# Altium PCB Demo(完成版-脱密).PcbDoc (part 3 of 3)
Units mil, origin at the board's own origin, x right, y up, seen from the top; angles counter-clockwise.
Board outline 2165.35 x 1574.8 mil, 6 copper layers (TOP, GND02, ART03, ART04, PWR05, BOTTOM); 172 components, 0 nets, 834 pads, 541 vias.
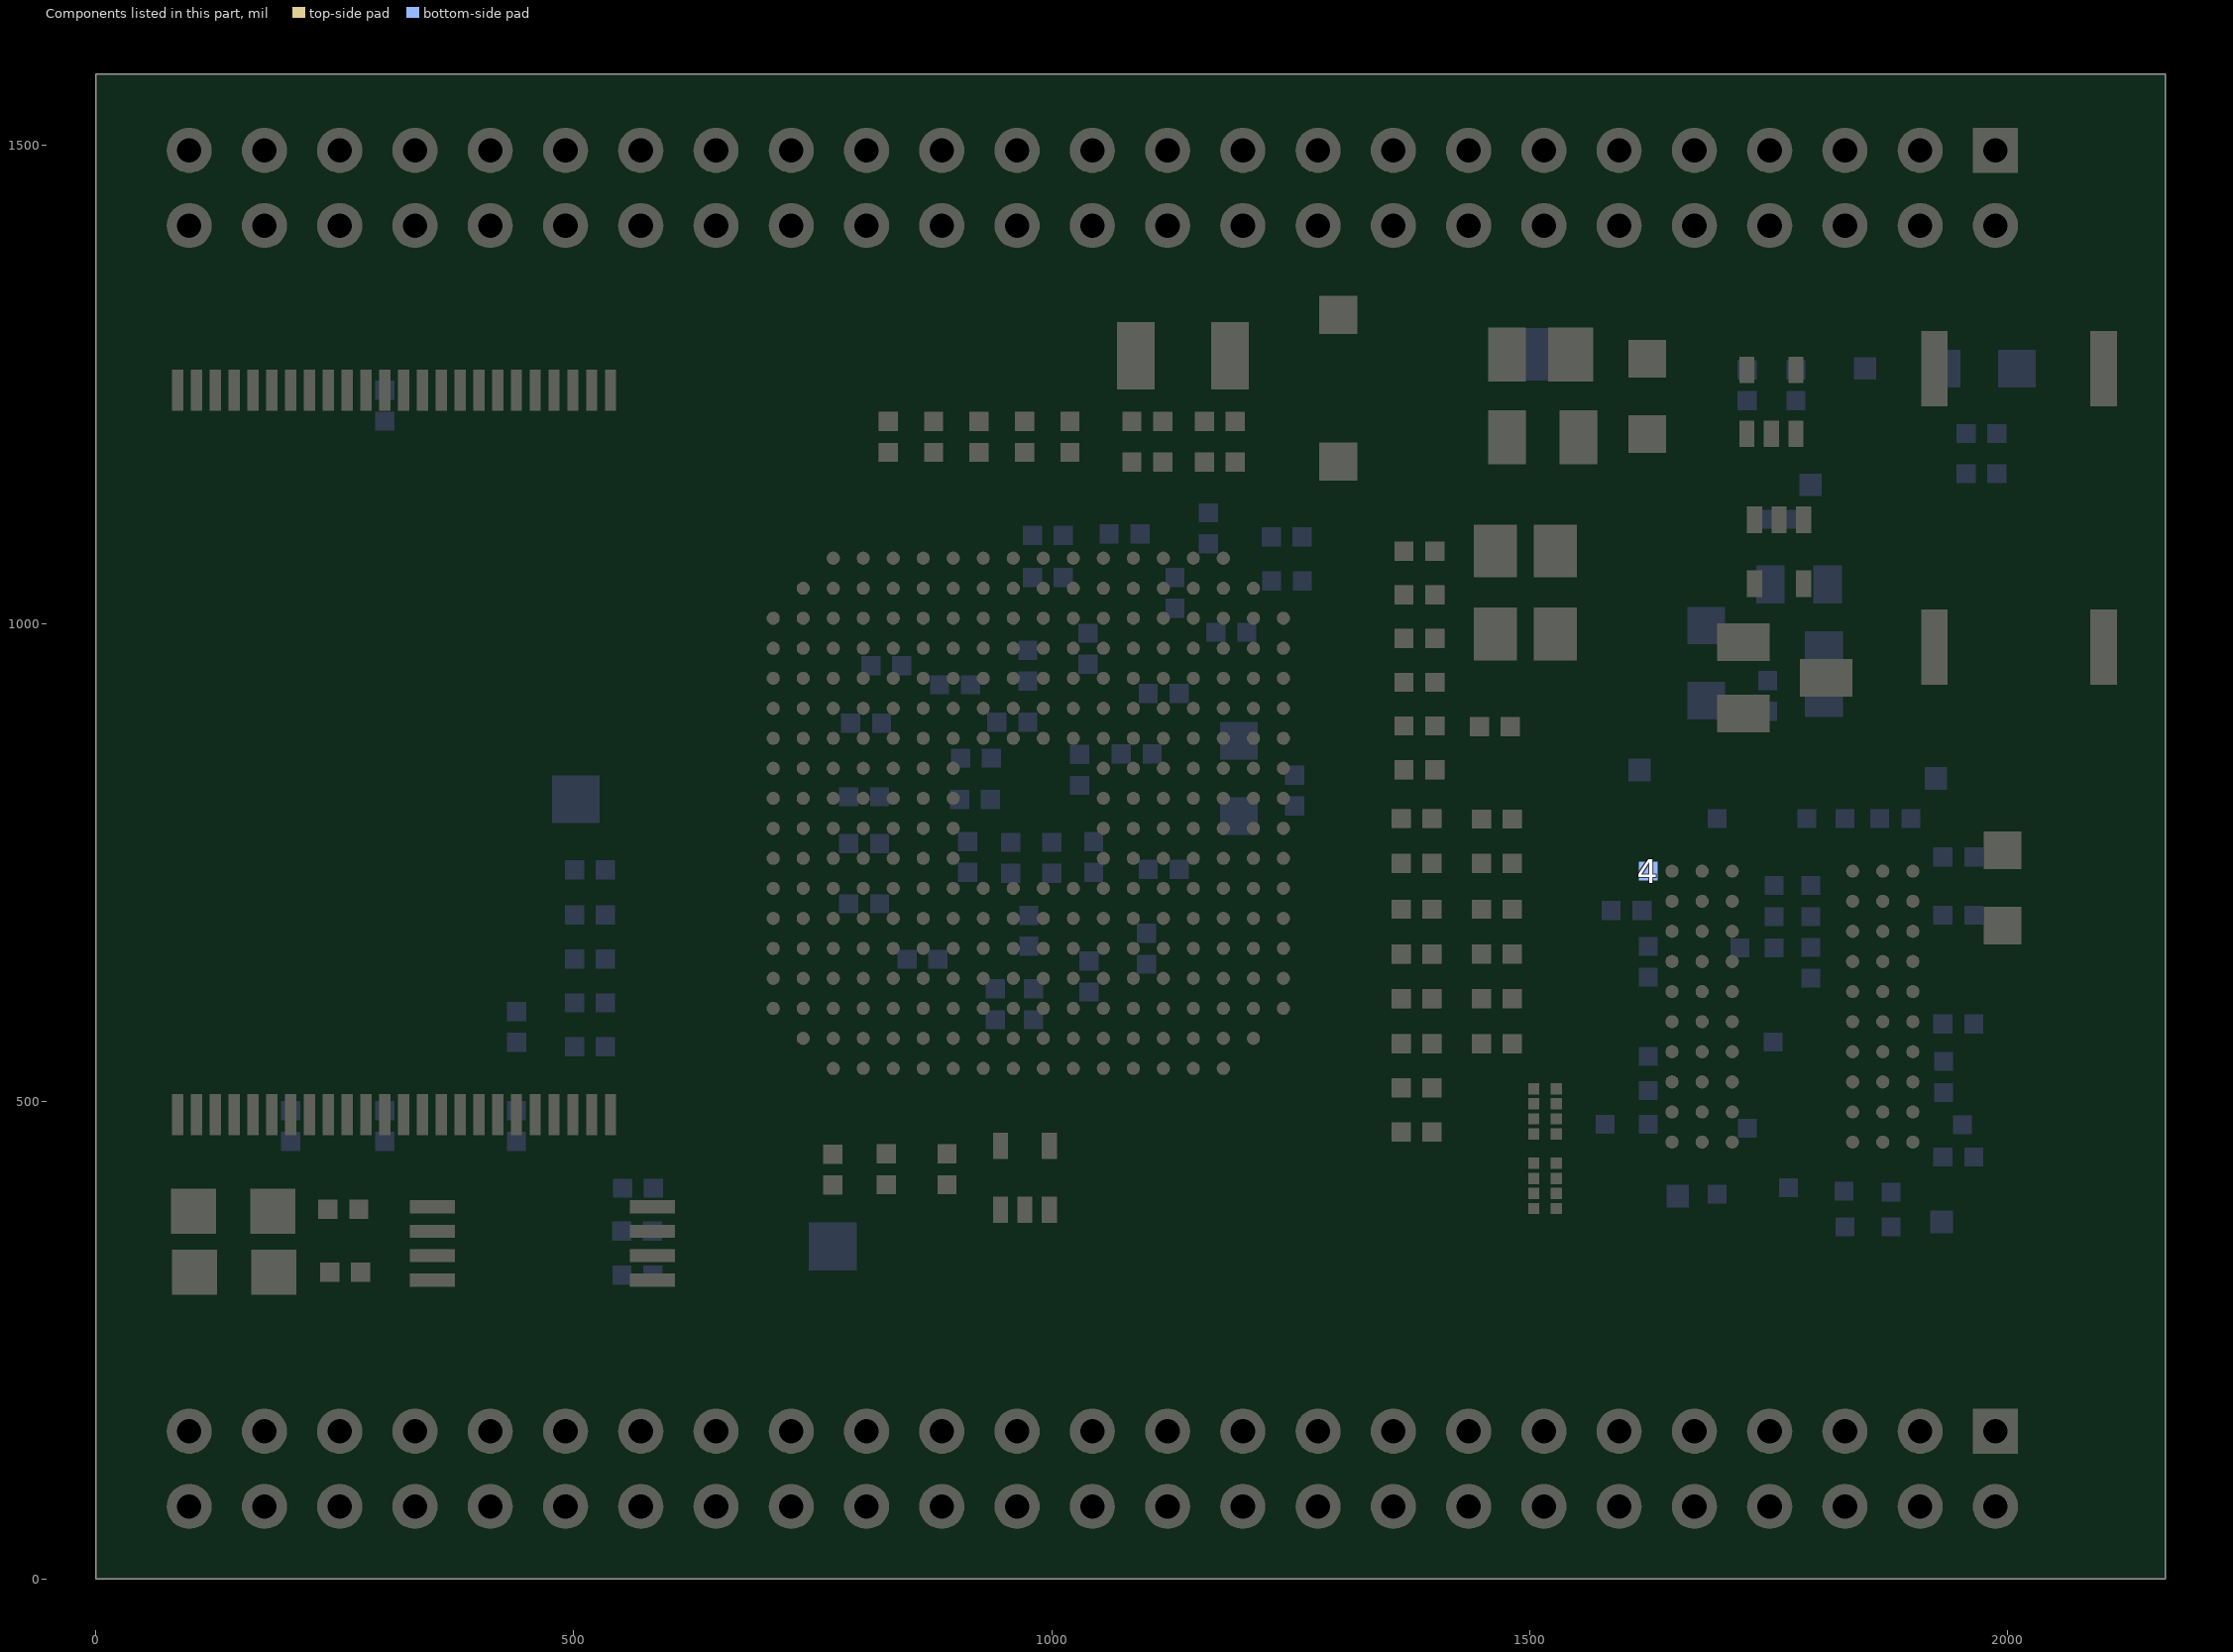
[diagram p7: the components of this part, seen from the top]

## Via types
v1: diameter 16, hole 8, TOP to BOTTOM, tented both sides, 541 vias

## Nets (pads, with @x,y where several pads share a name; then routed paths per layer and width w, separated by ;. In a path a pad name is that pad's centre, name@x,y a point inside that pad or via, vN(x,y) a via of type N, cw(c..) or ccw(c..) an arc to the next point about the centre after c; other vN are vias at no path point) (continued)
copper on no net: (continued)
  ART04 w6.2: 97.6,1416.26 97.01,1415.67 97.01,1367.73 111.01,1353.73 111.01,1164.73 165.01,1110.73 165.01,897.73 206.01,856.73 206.01,633.73 274.01,565.73 v1(385.01,565.73) 450.01,565.73 498.01,517.73 723.33,517.73 v1(724.3,518.7) ; 97.6,1495 141.01,1451.59 141.01,1356.73 ; v1(125.01,1073.73) 125.01,879.73 168.01,836.73 168.01,527.73 223.01,472.73 308.01,472.73 374.01,406.73 400.01,406.73 423.01,383.73 643.01,383.73 655.01,395.73 738.01,395.73 756.01,413.73 834.01,413.73 897,476.72 v1(897,503) ; v1(126.01,1120.73) 146.01,1100.73 146.01,888.73 187.01,847.73 187.01,630.73 270.01,547.73 444.01,547.73 492.01,499.73 739.01,499.73 775.01,535.73 804.13,535.73 v1(818.5,550.1) ; 141.01,1361.73 141.01,1356.73 ; 176.34,1416.26 178.01,1414.59 178.01,1338.73 142.01,1302.73 142.01,1173.73 201.01,1114.73 201.01,918.73 539.01,580.73 662.01,580.73 677.01,565.73 708.53,565.73 v1(724.3,581.5) ; 176.34,1495 215.01,1456.33 215.01,1346.73 162.01,1293.73 162.01,1178.73 177.01,1163.73 220.01,1163.73 241.01,1142.73 241.01,936.73 565.01,612.73 653.01,612.73 673.01,632.73 705.01,632.73 724.84,612.9 v1(787.1,612.9) ; v1(184.1,1204.87) 204.24,1184.73 244.01,1184.73 255.01,1173.73 255.01,1075.73 ; v1(203.69,555.14) 255.1,503.73 364.01,503.73 393.01,474.73 439.01,474.73 457.84,455.9 v1(691.9,455.9) v1@692.9,455.9 ; v1(203.78,525.14) 240.19,488.73 355.01,488.73 385.01,458.73 430.01,458.73 470.01,418.73 565.01,418.73 585.01,438.73 648.01,438.73 657.01,429.73 700.01,429.73 724.3,454.02 v1(724.3,455.9) ; v1@223.01,1118.73 223.01,928.73 554.54,597.2 859.54,597.2 865.6,591.14 865.6,565.8 v1(881.3,550.1) ; v1(223.47,1204.87) 249.87,1204.87 273.01,1181.73 273.01,963.73 560.01,676.73 654.01,676.73 670.74,660 890.74,660 900.01,650.73 908.01,650.73 912.7,646.04 v1(912.7,612.9) ; 255.01,1090.73 255.01,1075.73 ; 255.08,1416.26 257.01,1414.33 257.01,1366.73 ; 255.08,1495 292.01,1458.07 292.01,1387.73 274.01,1369.73 274.01,1261.73 386.86,1148.88 386.86,983.88 573.01,797.73 787.01,797.73 818.5,829.22 v1(818.5,864.1) ; 257.01,1373.73 257.01,1366.73 ; v1(285.01,589.73) 462.01,589.73 513.01,538.73 747.01,538.73 757.01,548.73 785.73,548.73 v1(818.5,581.5) ; v1(315.01,1084.87) 295.01,1064.87 295.01,972.73 576.34,691.4 922.34,691.4 928.4,685.34 928.4,597.2 v1(912.7,581.5) ; v1(316.01,1048.73) 316.01,976.73 569.94,722.8 683.94,722.8 703.01,703.73 802.01,703.73 821.08,722.8 950.94,722.8 959.8,713.94 959.8,597.2 v1(912.7,550.1) ; 333.82,1416.26 333.82,1375.92 357.01,1352.73 357.01,1210.73 404.71,1163.03 404.71,991.03 579.01,816.73 776.01,816.73 787.1,827.82 v1(787.1,864.1) ; 333.82,1495 374.01,1454.81 374.01,1217.73 422.56,1169.18 422.56,1000.18 577.01,845.73 705.93,845.73 v1(724.3,864.1) ; v1(350.32,1124.87) 350.32,988.42 584.54,754.2 935.54,754.2 972.01,717.73 972.01,583.73 928.4,540.12 v1(928.4,503) ; v1(365.01,525.73) 398.01,492.73 451.01,492.73 470.01,473.73 661.01,473.73 788.01,473.73 834.2,519.92 834.2,565.8 v1(849.9,581.5) ; v1(400.63,525.14) 419.04,506.73 461.01,506.73 481.01,486.73 689.01,486.73 755.13,486.73 v1(787.1,518.7) ; v1(411.01,426.73) 439.01,398.73 571.01,398.73 595.01,422.73 641.01,422.73 647.01,416.73 731.01,416.73 742.51,428.23 818.51,428.23 849.9,459.62 v1(849.9,550.1) ; 412.56,1495 458.26,1449.3 458.26,1160.73 ; 414.01,1421.73 414.01,1223.73 440.41,1197.33 440.41,1010.33 586.64,864.1 v1(661.5,864.1) ; 458.26,1288.73 458.26,1160.73 ; 491.3,1416.26 495.01,1412.55 495.01,1004.73 596.01,903.73 747.47,903.73 v1(755.7,895.5) ; 491.3,1495 531.01,1455.29 531.01,1025.99 v1(630.1,926.9) ; 570.04,1416.26 569.01,1415.23 569.01,1014.73 661.51,922.23 767.98,922.23 779.01,911.2 802.8,911.2 v1(818.5,926.9) ; 570.04,1495 609.01,1456.03 609.01,1388.73 592.01,1371.73 592.01,1011.73 664.51,939.23 774.77,939.23 v1(787.1,926.9) ; 647.01,1414.49 648.78,1416.26 648.78,1389.5 612.01,1352.73 612.01,1012.73 666.44,958.3 v1(724.3,958.3) ; 648.78,1495 686.01,1457.77 686.01,1386.73 630.01,1330.73 630.01,1015.73 674.01,971.73 706.33,971.73 v1(724.3,989.7) ; v1(692.9,864.1) 673.27,883.73 591.01,883.73 458.26,1016.48 458.26,1160.73 ; v1(692.9,989.7) 678.04,989.7 648.01,1019.73 648.01,1302.73 728.01,1382.73 728.01,1415.77 727.52,1416.26 ; v1(692.9,1021.1) 692.9,1262.62 806.26,1375.98 806.26,1416.26 809.73,1419.73 810.01,1419.73 ; v1(724.3,1115.3) 724.3,1239.02 858.01,1372.73 920.21,1372.73 963.74,1416.26 ; 727.52,1495 764.01,1458.51 764.01,1376.73 669.01,1281.73 669.01,1019.73 683.34,1005.4 740,1005.4 v1(755.7,989.7) ; v1(755.7,864.1) 776.02,884.42 810.7,884.42 837.48,911.2 956.48,911.2 966.01,920.73 966.01,1042.73 1008.01,1084.73 1088.14,1084.73 1123.14,1119.73 1260.01,1119.73 1297.01,1156.73 1297.01,1247.73 1317.01,1267.73 1317.01,1303.73 ; v1(755.7,1021.1) 708.01,1068.79 708.01,1251.73 842.01,1385.73 842.01,1459.25 806.26,1495 ; v1(755.7,1115.3) 740.01,1130.99 740.01,1225.73 869.01,1354.73 956.01,1354.73 1000.01,1398.73 1000.01,1458.73 963.74,1495 ; v1@755.7,1146.7 v1(755.7,1151) 755.7,1219.42 874.35,1338.07 964.29,1338.07 984.48,1358.26 1042.48,1416.26 ; v1@784.95,1148.85 772.01,1161.79 772.01,1207.73 886.88,1322.6 980.88,1322.6 1038.01,1379.73 1063.01,1379.73 1083.01,1399.73 1083.01,1449.73 1046.01,1486.73 ; v1(787.1,581.5) 769.33,563.73 742.01,563.73 732.01,553.73 664.01,553.73 652.51,565.23 522.51,565.23 444.01,643.73 v1(227.01,643.73) 227.01,866.73 182.01,911.73 182.01,1116.76 127.01,1171.76 127.01,1259.73 127.01,1313.73 141.01,1327.73 141.01,1356.73 ; v1(787.1,738.5) 765.33,716.73 708.01,716.73 686.24,738.5 575.24,738.5 336.01,977.73 336.01,1096.73 327.01,1105.73 307.01,1105.73 290.01,1122.73 290.01,1196.73 257.01,1229.73 257.01,1366.73 ; v1(787.1,1021.1) 787.1,1080.82 845.01,1138.73 845.01,1180.73 897.01,1232.73 897.01,1253.73 930.01,1286.73 986.01,1286.73 1045.01,1345.73 1076.01,1345.73 1108.89,1378.61 1145.89,1378.61 1159.01,1391.73 1159.01,1457.21 1121.22,1495 ; v1(787.1,1115.3) 809.01,1137.21 809.01,1189.73 852.01,1232.73 852.01,1248.73 872.52,1269.24 888.52,1269.24 922.09,1302.81 980.09,1302.81 1039.01,1361.73 1066.69,1361.73 1121.22,1416.26 ; v1(818.5,1021.1) 834.2,1036.8 834.2,1105.33 860.01,1131.14 860.01,1165.73 907.01,1212.73 939.01,1212.73 948.01,1221.73 948.01,1248.73 968.01,1268.73 990.01,1268.73 1051.01,1329.73 1089.01,1329.73 1125.01,1365.73 1185.01,1365.73 1199.96,1380.68 1199.96,1416.26 ; v1(849.9,801.3) 891.01,801.3 950.01,860.3 950.01,880.73 984.01,914.73 984.01,1039.73 1012.48,1068.2 1123.01,1068.2 1156.54,1101.73 1267.01,1101.73 1310.01,1144.73 1310.01,1238.73 1333.01,1261.73 1333.01,1310.73 ; v1(849.9,1021.1) 869.01,1040.21 869.01,1076.73 891.88,1099.6 961.88,1099.6 982.01,1119.73 1048.01,1119.73 1102.01,1173.73 1137.01,1173.73 1239.01,1173.73 1258.01,1192.73 1258.01,1262.73 1249.01,1271.73 1249.01,1353.73 1237.01,1365.73 1237.01,1453.73 1202.01,1488.73 ; v1(881.3,581.5) 897,597.2 897,621.74 890.14,628.6 732.14,628.6 715.01,645.73 661.01,645.73 642.01,626.73 583.01,626.73 255.01,954.73 255.01,1075.73 ; v1(881.3,989.7) 928.4,1036.8 928.4,1062.12 934.48,1068.2 971.48,1068.2 1006.01,1102.73 1083.01,1102.73 1139.01,1158.73 1258.01,1158.73 1274.01,1174.73 1274.01,1411.57 1278.7,1416.26 ; v1(1006.9,612.9) 1006.9,576.62 995.01,564.73 995.01,441.73 1120.01,316.73 1812.01,316.73 1916.73,421.45 v1(1916.73,473.07) ; v1(1038.3,581.5) 1038.3,594.44 1033.01,599.73 1029.01,599.73 1022.27,592.99 1022.27,565.47 1010.01,553.21 1010.01,446.73 1126.01,330.73 1806.01,330.73 1903.01,427.73 1903.01,450.73 1897.01,456.73 1859.01,456.73 1853.74,462 v1(1853.74,473.07) ; v1(1069.7,518.7) 1069.7,455.04 1153.01,371.73 1170.01,371.73 1174.56,371.73 1179.11,376.28 1179.11,383.18 1183.66,387.73 1192.76,387.73 1197.31,383.18 1197.31,376.28 1201.86,371.73 1210.96,371.73 1215.51,376.28 1215.51,383.18 1220.06,387.73 1229.16,387.73 1233.71,383.18 1233.71,376.28 1238.26,371.73 1247.36,371.73 1251.91,376.28 1251.91,383.18 1256.46,387.73 1265.56,387.73 1270.11,383.18 1270.11,376.28 1274.66,371.73 1283.76,371.73 1288.31,376.28 1288.31,383.18 1292.86,387.73 1301.96,387.73 1306.51,383.18 1306.51,376.28 1311.06,371.73 1320.16,371.73 1324.71,376.28 1324.71,383.18 1329.26,387.73 1338.36,387.73 1342.91,383.18 1342.91,376.28 1347.46,371.73 1356.56,371.73 1361.11,376.28 1361.11,383.18 1365.66,387.73 1374.76,387.73 1379.31,383.18 1379.31,376.28 1383.86,371.73 1392.96,371.73 1397.51,376.28 1397.51,383.18 1402.06,387.73 1411.16,387.73 1415.71,383.18 1415.71,376.28 1420.26,371.73 1427.01,371.73 1706.01,371.73 1791.6,457.32 1832.42,457.32 1838.01,451.73 1838.01,444.73 1834.85,441.57 v1(1822.24,441.57) ; v1(1069.7,550.1) 1056.67,537.07 1056.35,537.07 1042.01,522.73 1042.01,515.73 1053.01,504.73 1053.01,490.73 1043.01,480.73 1043.01,465.73 1053.01,455.73 1053.01,445.73 1140.01,358.73 1743.01,358.73 1748.01,363.73 1748.01,389.73 1782.01,423.73 1789.01,423.73 1793.01,419.73 1793.01,367.73 1798.01,362.73 1815.01,362.73 1824.01,371.73 1824.01,389.73 1816.01,397.73 1816.01,406.73 1822.01,412.73 1838.01,412.73 1844.01,406.73 1859.01,406.73 1869.01,416.73 1869.01,426.3 v1(1853.74,441.57) v1@1851.85,441.57 ; v1(1069.7,612.9) 1069.7,614.04 1043.01,640.73 1031.01,640.73 1026.01,635.73 1026.01,618.73 1029.01,615.73 1043.01,615.73 1054.01,604.73 1054.01,568.73 1026.01,540.73 1026.01,451.73 1134.01,343.73 1759.01,343.73 1771.01,355.73 v1(1771.01,386.73) v1@1771.01,389.73 ; v1(1069.7,989.7) 1085.4,1005.4 1353.01,1005.4 1382.34,1034.73 1558.01,1034.73 1575.01,1051.73 1624.01,1051.73 1646.29,1074.01 v1(1735,1074.01) ; v1(1069.7,1021.1) 1085.4,1036.8 1234.08,1036.8 1348.55,1151.27 1348.55,1310.27 1394.01,1355.73 1394.01,1458.43 1357.44,1495 ; v1(1101.1,518.7) 1101.1,477.64 1159.81,418.93 1500.81,418.93 1507.01,412.73 1507.01,406.73 1513.01,400.73 1525.01,400.73 1532.01,407.73 1532.01,429.73 1527.01,434.73 1513.01,434.73 1505.01,442.73 1505.01,452.73 1509.6,457.32 1527.01,457.32 1531.56,457.32 1536.11,461.87 1536.11,472.29 1540.66,476.84 1549.76,476.84 1554.31,472.29 1554.31,461.87 1558.86,457.32 1567.96,457.32 1572.51,461.87 1572.51,472.29 1577.06,476.84 1586.16,476.84 1590.71,472.29 1590.71,461.87 1595.26,457.32 1604.36,457.32 1608.91,461.87 1608.91,472.29 1613.46,476.84 1622.56,476.84 1627.11,472.29 1627.11,461.87 1631.66,457.32 1660.01,457.32 1712.01,457.32 v1(1727.76,441.57) ; v1(1101.1,581.5) 1085.4,565.8 1085.4,465.34 1147.01,403.73 1424.01,403.73 1441.01,386.73 1593.56,386.73 1598.11,391.28 1598.11,424.18 1602.66,428.73 1611.76,428.73 1616.31,424.18 1616.31,391.28 1620.86,386.73 1629.96,386.73 1634.51,391.28 1634.51,424.18 1639.06,428.73 1648.16,428.73 1652.71,424.18 1652.71,391.28 1657.26,386.73 1667.71,386.73 1672.26,391.28 1672.26,424.18 1676.81,428.73 1685.91,428.73 1690.46,424.18 1690.46,391.28 ; v1(1132.5,518.7) 1132.5,490.24 1141.51,481.23 1160.51,481.23 1167.51,474.23 1167.51,455.23 1174.01,448.73 1186.56,448.73 1191.11,453.28 1191.11,482.18 1195.66,486.73 1204.76,486.73 1209.31,482.18 1209.31,453.28 1213.86,448.73 1222.96,448.73 1227.51,453.28 1227.51,482.18 1232.06,486.73 1241.16,486.73 1245.71,482.18 1245.71,453.28 1250.26,448.73 1259.36,448.73 1263.91,453.28 1263.91,482.18 1268.46,486.73 1277.56,486.73 1282.11,482.18 1282.11,453.28 1286.66,448.73 1295.76,448.73 1300.31,453.28 1300.31,482.18 1304.86,486.73 1313.96,486.73 1318.51,482.18 1318.51,453.28 1323.06,448.73 1332.16,448.73 1336.71,453.28 1336.71,482.18 1341.26,486.73 1350.36,486.73 1354.91,482.18 1354.91,453.28 1359.46,448.73 1368.71,448.73 1373.26,453.28 1373.26,482.18 1377.81,486.73 1386.91,486.73 1391.46,482.18 1391.46,453.28 1396.01,448.73 1406.01,448.73 1410.01,452.73 1410.01,486.73 1421.01,497.73 1496.01,497.73 1508.01,509.73 1541.01,509.73 1552.01,520.73 1564.01,520.73 1573.01,511.73 1590.01,511.73 1599.01,520.73 1616.01,520.73 1625.01,511.73 1641.01,511.73 1649.6,520.32 1673.42,520.32 1679.01,514.73 1679.01,506.73 1676.85,504.57 v1(1664.76,504.57) ; v1(1132.5,550.1) 1132.5,562.22 1136.01,565.73 1144.01,565.73 1148.2,561.54 1148.2,511.54 1157.01,502.73 1312.01,502.73 1344.01,534.73 1392.01,534.73 1409.01,551.73 1428.01,551.73 1441.01,564.73 1460.01,564.73 1473.01,551.73 1775.01,551.73 1786.01,540.73 1802.01,540.73 1813.01,551.73 1833.01,551.73 1838.01,546.73 1838.01,526.73 1831.6,520.32 1768.6,520.32 1764.01,515.73 1764.01,493.73 1768.92,488.82 1832.92,488.82 1837.99,483.75 1837.99,476.71 1834.35,473.07 v1(1822.24,473.07) ; v1(1132.5,612.9) 1116.8,597.2 1116.8,482.94 1165.01,434.73 1419.01,434.73 1437.01,452.73 1468.73,452.73 v1(1484.01,468.01) ; v1(1163.9,518.7) 1304.98,518.7 1336.01,549.73 1383.01,549.73 1398.7,565.42 1410.7,565.42 1424.01,578.73 1534.01,578.73 1547.01,591.73 1581.27,591.73 1591,582 1626.28,582 1641.01,596.73 1695.01,596.73 1725.01,566.73 1818.01,566.73 1841.01,589.73 1855.01,589.73 1863.01,581.73 1875.01,581.73 1883.01,589.73 1911.16,589.73 1915.71,585.18 1915.71,542.28 1920.26,537.73 1929.36,537.73 1933.91,542.28 1933.91,585.18 1938.46,589.73 1954.01,589.73 1960.01,583.73 1960.01,511.73 1954.01,505.73 1912.6,505.73 1898.01,520.32 1869.49,520.32 v1(1853.74,504.57) ; v1(1163.9,550.1) 1180.27,533.73 1295.01,533.73 1325.39,564.11 1368.39,564.11 1380.01,575.73 1380.01,591.73 1388.02,599.74 1499,599.74 1506.01,592.73 1524.73,592.73 1540.73,608.73 1585.27,608.73 1598,596 1617.28,596 1633.01,611.73 1706.27,611.73 1737.27,580.73 1812.01,580.73 1838.01,606.73 1966.01,606.73 1977.01,595.73 1977.01,556.18 1981.56,551.63 1992.46,551.63 1997.01,547.08 1997.01,537.98 1992.46,533.43 1981.56,533.43 1977.01,528.88 1977.01,503.73 ; v1(1195.3,707.1) 1179.6,691.4 1123.34,691.4 1116.8,697.94 1116.8,715.52 1124.08,722.8 1257.08,722.8 1275.01,740.73 1275.01,754.73 1287.01,766.73 1627.01,766.73 1653.01,740.73 1704.01,740.73 1712.01,732.73 1712.01,709.3 v1(1696.26,693.54) ; v1(1195.3,738.5) 1195.3,767.3 1229.73,801.73 1299.01,801.73 1317.01,819.73 1365.01,819.73 1383.01,801.73 1706.16,801.73 1710.71,797.18 1710.71,780.28 1715.26,775.73 1724.36,775.73 1728.91,780.28 1728.91,797.18 1733.46,801.73 1805.01,801.73 1815.01,791.73 1815.01,779.73 1810.01,774.73 1755.01,774.73 1747.01,766.73 1747.01,744.29 v1(1727.76,725.03) ; v1(1226.71,675.7) 1206.88,655.88 1193.56,655.88 1189.01,651.33 1189.01,642.23 1193.56,637.68 1206.46,637.68 1211.01,633.13 1211.01,597 1216.01,592 1230,592 1235,587 1235,581 1228,574 1216.01,574 1211.01,569 1211.01,561.99 1219,554 1259.83,554 1289.11,583.28 1289.11,622.18 1293.66,626.73 1302.76,626.73 1307.31,622.18 1307.31,583.28 1311.86,578.73 1320.96,578.73 1325.51,583.28 1325.51,622.18 1330.06,626.73 1339.16,626.73 1343.71,622.18 1343.71,583.28 1348.26,578.73 1358.01,578.73 1365.01,585.73 1365.01,602 1376.48,613.47 1449.92,613.47 1467,630.55 v1(1664.76,630.55) ; v1(1226.71,707.1) 1242.41,691.4 1271.4,691.4 1305,725 1350.74,725 1370.01,705.73 1385.01,705.73 1398.01,718.73 1436.01,718.73 1447.01,707.73 1465.01,707.73 1476.01,718.73 1527.01,718.73 1537.01,708.73 1537.01,685.73 1546.01,676.73 1798.01,676.73 1805.01,683.73 1805.01,689.73 1799.01,695.73 1782.01,695.73 1776.01,701.73 1776.01,709.73 1782.01,715.73 1800.01,715.73 1805.01,720.73 1805.01,729.73 1796.01,738.73 1768.01,738.73 1755.01,725.73 1755.01,700.73 1747.82,693.54 v1(1727.76,693.54) ; v1(1226.71,738.5) 1272.93,784.73 1668.06,784.73 v1(1696.26,756.53) ; v1(1258.1,675.7) 1283.7,675.7 1319,711 1342,711 1358.27,694.73 1383,694.73 1392.73,685 1442.74,685 1465.7,662.04 1474.56,662.04 1479.11,666.59 1479.11,695.49 1483.66,700.04 1492.76,700.04 1497.31,695.49 1497.31,666.59 1501.86,662.04 1791.96,662.04 1822,632 1822,613 1816.79,607.79 1807.21,607.79 1802,613 1802,621 1796,627 1787,627 1782,622 1782,605 1774.73,597.73 1767,597.73 1759.26,605.47 v1(1759.26,630.54) ; v1(1258.1,707.1) 1263.03,707.1 1306.66,750.73 1352.16,750.73 1356.71,746.18 1356.71,737.28 1361.26,732.73 1370.36,732.73 1374.91,737.28 1374.91,746.18 1379.46,750.73 1388.56,750.73 1393.11,746.18 1393.11,737.28 1397.66,732.73 1443.16,732.73 1447.71,737.28 1447.71,746.18 1452.26,750.73 1461.36,750.73 1465.91,746.18 1465.91,737.28 1470.46,732.73 1479.56,732.73 1484.11,737.28 1484.11,746.18 1488.66,750.73 1497.76,750.73 1502.31,746.18 1502.31,737.28 1506.86,732.73 1530.01,732.73 1535.01,737.73 1535.01,746.73 1539.01,750.73 1549.01,750.73 1552.01,747.73 1552.01,697.73 1558.01,691.73 1568.56,691.73 1573.11,696.28 1573.11,743.18 1577.66,747.73 1586.76,747.73 1591.31,743.18 1591.31,696.28 1595.86,691.73 1604.96,691.73 1609.51,696.28 1609.51,743.18 1614.06,747.73 1623.16,747.73 1627.71,743.18 1627.71,696.28 1632.26,691.73 1641.01,691.73 1645.01,695.73 1645.01,702.73 1651.57,709.29 1680.51,709.29 v1(1696.26,725.03) ; v1@1260.09,646.3 v1(1258.1,644.3) 1258.1,631.82 1255.01,628.73 1247.01,628.73 1243.01,632.73 1243.01,655.73 1247.01,659.73 1271.01,659.73 1289.01,641.73 1300.01,641.73 1309.01,650.73 1321.01,650.73 1330.01,641.73 1352.55,641.73 1357.1,646.28 1357.1,669.18 1361.65,673.73 1370.75,673.73 1375.3,669.18 1375.3,646.28 1379.85,641.73 1394.01,641.73 1398.58,646.3 1712.01,646.3 v1(1727.76,630.54) ; 1278.7,1495 1317.01,1456.69 1317.01,1303.73 ; 1317.01,1308.73 1317.01,1303.73 ; 1333.01,1315.73 1333.01,1310.73 ; 1357.44,1416.26 1357.44,1362.16 1333.01,1337.73 1333.01,1310.73 ; v1(1427.39,514.01) 1417.29,514.01 1405.01,501.73 1350.01,501.73 1346.01,505.73 1346.01,514.73 1352.01,520.73 1398.01,520.73 1413.34,536.06 1441.16,536.06 1445.71,531.51 1445.71,518.61 1450.26,514.06 1459.36,514.06 1463.91,518.61 1463.91,531.51 1468.46,536.06 1495.68,536.06 1506.01,525.73 1528.01,525.73 1538.34,536.06 v1(1664.76,536.06) ; 1436.18,1416.26 1477,1375.44 1477,1311.73 v1(1552,1236.73) ; v1(1449.01,822.73) v1(1566.01,822.73) ; v1(1576.29,567.56) 1638.01,567.56 1654.18,583.73 1680.09,583.73 v1(1696.26,567.56) v1@1696.26,571.48 ; 1692.06,389.68 1690.46,391.28 ; v1(1696.26,473.07) 1761.67,473.07 1769.01,465.73 1769.01,456.73 1736.37,424.09 1721.37,424.09 1711.01,413.73 1711.01,398.73 1700.01,387.73 1694.01,387.73 1690.46,391.28 ; v1(1885.23,504.57) 1897.07,492.73 1930.16,492.73 1934.71,488.18 1934.71,475.28 1939.26,470.73 1948.36,470.73 1952.91,475.28 1952.91,488.18 1957.46,492.73 1968.01,492.73 1977.01,501.73
  ART04 w10: 972,532.73 972,558.83 ; v1(1430,847) 1572.74,847 1582.01,837.73 v1@1790.01,837.73
  ART04 w15: v1(1101.1,895.5) 1101.1,878.64 1110.01,869.73 1582.01,869.73 1591.01,860.73 1677.74,860.73 1690.01,873 v1(1742.01,873) v1(1803.01,873) ; v1(1132.5,895.5) 1256.01,895.5 1277.24,916.73 1417.01,916.73 1428.01,905.73 1483,905.73 1496,918.73 1570.01,918.73 v1(1602.01,886.73) v1(1628.01,886.73) v1(1651.01,886.73)
  BOTTOM w5: 771.01,723.31 771.01,754.2 ; v1(1195.3,612.9) 1195.3,627.3 1200,632 1200,636 1196,640 1186,640 1183,643 1183,654 1189,660 1268,660 1280.5,672.5 1321.5,672.5 v1(1330,664) ; v1(1226.98,770.18) 1211.01,754.21 1211.01,698.39 1218,691.4 1268.6,691.4 1275.5,684.5 1321.5,684.5 v1(1330,693) ; v1(1423,669) 1432,678 1446.97,678 1459,690.03 1459,722.03 1461.97,725 1481.03,725 1490,716.03 1490,629.24 1486.26,625.5 1458.76,625.5 1448,614.74 1448,580.26 1458.76,569.5 1472.26,569.5 1476,565.76 1476,556.24 1472.26,552.5 1458.76,552.5 1448,541.74 1448,503.03 1467.03,484 1511.97,484 1528,500.03 1528,577.03 1537.97,587 1553.74,587 1564.5,597.76 1564.5,655.26 1568.24,659 1577.76,659 1581.5,655.26 1581.5,597.76 1592.26,587 1705,587 1715,577 1715,554.8 v1(1696.26,536.06) ; v1(1423,700.91) 1433.91,690 1442,690 1447,695 1447,727 1457,737 1486,737 1502,721 1502,624.26 1491.24,613.5 1463.74,613.5 1460,609.76 1460,585.24 1463.74,581.5 1477.24,581.5 1488,570.74 1488,551.26 1477.24,540.5 1463.74,540.5 1460,536.76 1460,508 1472,496 1507,496 1516,505 1516,582 1533,599 1548.76,599 1552.5,602.74 1552.5,660.24 1563.26,671 1582.74,671 1593.5,660.24 1593.5,602.74 1597.24,599 1709.97,599 1727.76,581.21 v1(1727.76,536.06)
  BOTTOM w5.7: 203.73,490.14 203.73,525.09 v1(203.78,525.14) ; v1(385.01,565.73) 413.15,593.87 440.01,593.87 ; 439.95,490.14 v1(440,525.14) v1(440,525.14) 440,561.58 ; 500.72,742 500.72,814.72 502,816 ; 533,557 557.5,581.5 v1(692.9,581.5) ; 533,603 538.8,597.2 802.8,597.2 v1(818.5,612.9) v1@818.5,615.11 ; 533,649 537.7,644.3 v1(630.1,644.3) ; 533,695 552.74,695 571.01,676.73 636.28,676.73 653.01,660 708.6,660 v1(724.3,675.7) ; 533,742 583.6,691.4 740,691.4 v1(755.7,675.7) ; 582.59,318 582.31,318.28 582.31,364 625.82,364 v1(626,364.18) ; v1(755.7,581.5) 803.12,534.08 v1(803.12,444.6) ; 771,348 v1(771,385.74) ; v1(827.01,476.73) 827.01,529.54 834.2,536.73 834.2,597.2 v1(849.9,612.9) ; 829,1179 v1(829,1151) 865.6,1114.4 865.6,1101.73 896.81,1070.52 896.81,973.81 v1(881.3,958.3) ; v1(876.5,1151) 888.3,1151 v1(924,1115.3) ; v1(924,1154) 941.01,1136.99 941.01,1104.73 928.4,1092.12 928.4,1005.4 v1(944.1,989.7) ; v1@971.5,1151 v1(971.5,1154) 971.5,1179 ; 975,1043.14 979.86,1048 ; v1@1019,1151 v1(1019,1154) 1019,1179 ; v1(1101.1,958.3) 1116.8,974 1116.8,1003.66 1129,1015.86 ; v1(1132.5,675.7) 1132.5,642.22 1116.8,626.52 1116.8,502 1130,488.8 1130,413 1167,376 1428.71,376 v1(1456.01,403.3) ; v1(1163.9,612.9) 1179.6,597.2 1187.8,597.2 1195,590 1195,579 1179.6,563.6 1179.6,462.4 1207.21,434.79 1220,434.79 1238.43,434.79 1242.85,430.36 1242.85,417.76 1247.28,413.34 1256.12,413.34 1260.55,417.76 1260.55,430.36 1264.97,434.79 1273.82,434.79 1278.25,430.36 1278.25,417.76 1282.68,413.34 1291.53,413.34 1295.95,417.76 1295.95,430.36 1300.38,434.79 1309.22,434.79 1313.65,430.36 1313.65,417.76 1318.07,413.34 1326.93,413.34 1331.35,417.76 1331.35,430.36 1335.78,434.79 1344.62,434.79 1349.05,430.36 1349.05,417.76 1353.47,413.34 1362.32,413.34 1366.75,417.76 1366.75,430.36 1371.18,434.79 1380.03,434.79 1384.45,430.36 1384.45,417.76 1388.88,413.34 1397.72,413.34 1402.15,417.76 1402.15,430.36 1406.57,434.79 1411,434.79 v1(1456.01,434.79) ; v1(1163.9,644.3) 1148.01,628.41 1148.01,423.99 1175,397 1186,397 1190.43,397 1194.85,401.43 1194.85,408.2 1199.28,412.63 1208.12,412.63 1212.55,408.2 1212.55,401.43 1216.97,397 1223,397 1423.27,397 1445,418.73 1468.58,418.73 v1(1484.01,403.3) ; v1(1163.9,926.9) 1179.8,911 1242,911 1292,861 1354.5,861 1368.5,847 ; v1(1163.9,958.3) 1179.6,942.6 1253.4,942.6 1303,893 v1(1339,893) ; v1(1195.3,550.1) 1195.3,467.7 1212.27,450.73 1362,450.73 1366.43,450.73 1370.85,455.16 1370.85,507.34 1375.28,511.77 1384.12,511.77 1388.55,507.34 1388.55,455.16 1392.97,450.73 1401.82,450.73 1406.25,455.16 1406.25,495.44 1410.68,499.87 1419.53,499.87 1423.95,495.44 1423.95,455.16 1428.38,450.73 1457,450.73 1468.07,450.73 v1(1484.01,434.79) ; v1(1195.3,926.9) 1246,926.9 1297.9,875 1350.78,875 1368.5,892.72 ; v1(1226.71,958.3) 1266.14,958.3 1304.45,920 1350.05,920 1368.5,938.45 ; v1(1226.71,1021.1) 1243.8,1004 1348.67,1004 1368.5,984.17 ; v1(1258.1,1021.1) 1277.1,1021.1 1303,1047 1351.4,1047 1368.5,1029.9 ; 1317.73,582.46 1324.43,582.46 ; v1(1341.41,801.13) 1360.26,801.13 1365.56,795.83 ; 1365.56,607.2 1365.56,587.28 1360.74,582.46 1350.97,582.46 1346.55,586.89 1346.55,606.03 1342.12,610.46 1333.28,610.46 1328.85,606.03 1328.85,586.89 1324.43,582.46 ; 1365.56,654.06 1340.1,628.6 1217.61,628.6 1211.01,622 1211.01,591.57 1215.43,587.15 1238.32,587.15 1242.75,582.72 1242.75,573.88 1238.32,569.45 1215.43,569.45 1211.01,565.03 1211.01,556.18 1215.43,551.75 1246.59,551.75 1251.01,547.32 1251.01,538.47 1246.59,534.05 1215.43,534.05 1211.01,529.62 1211.01,520.78 1215.43,516.35 1246.59,516.35 1251.01,511.93 1251.01,503.07 1246.59,498.65 1215.43,498.65 1211.01,494.22 1211.01,480.99 1223,469 1273,469 1277.43,469 1281.85,473.43 1281.85,500.4 1286.28,504.82 1295.12,504.82 1299.55,500.4 1299.55,473.43 1303.97,469 1341,469 1347,475 1347,525 1334,538 1293,538 1271,560 1271,571 1281.73,581.73 1288.43,581.73 1292.85,586.16 1292.85,605.3 1297.28,609.73 1306.12,609.73 1310.55,605.3 1310.55,586.16 1314.24,582.46 1324.43,582.46 ; 1397.84,560.34 v1(1397.84,583.73) 1397.84,607.2 ; 1397.84,654.06 1397.84,653.28 v1(1420.88,630.24) ; v1(1424.01,748.97) 1397.84,775.14 1397.84,795.83 1398.44,795.23 1449.56,795.23 ; v1@1513,1328 v1(1514,1328) 1514,1281.69 1565.04,1281.69 1684,1162.73 v1(1728.01,1162.73) ; v1(1548.29,403.3) 1563.92,418.93 1585.81,418.93 1593.01,411.73 1593.01,377.73 1627.01,343.73 1726.01,343.73 1748.82,366.54 1779.82,366.54 1791.01,377.73 1791.01,497.73 1813.6,520.32 1838,520.32 v1(1853.74,536.06) ; v1(1548.29,434.79) 1566.23,452.73 1598.01,452.73 1626.01,424.73 1626.01,387.73 1642.01,371.73 1711.01,371.73 1719.01,379.73 1719.01,408.73 1751.01,440.73 1751.01,508.01 1794.73,551.73 1869.56,551.73 v1(1885.23,536.06) ; v1@1551.01,1234.73 1551.4,1234.73 1551.4,1195.08 ; v1(1576.29,403.3) 1576.29,373.45 1620.01,329.73 1734.01,329.73 1755.01,350.73 1789.01,350.73 1804.01,365.73 1804.01,486.34 v1(1822.24,504.57) ; v1(1576.29,434.79) 1593.95,434.79 1610.01,418.73 1610.01,381.73 1634.01,357.73 1717.01,357.73 1734.01,374.73 1734.01,404.73 1771.01,441.73 1771.01,506.73 1800.34,536.06 v1(1822.24,536.06) ; 1579.01,475.73 1591.27,475.73 1609.68,457.32 1680.51,457.32 v1(1696.26,473.07) ; 1624.01,475.73 1626.67,473.07 v1(1664.76,473.07) v1@1662.1,475.73 ; 1624.01,511.23 1630.67,504.57 v1(1664.76,504.57) ; 1624.01,546.73 1650.03,520.71 1680.12,520.71 v1(1696.26,504.57) ; 1624.01,662.04 1664.76,662.04 v1(1696.26,693.54) ; 1624.01,740.73 1680.56,740.73 v1(1696.26,725.03) ; 1624.83,630.55 1624.01,629.73 1663.94,629.73 v1(1664.76,630.55) ; 1685,919 1696,908 ; 1685,997.74 1685,1031 1698,1044 1748.91,1044 1751.9,1041.01 1751.9,943.18 1749,940.28 ; 1696.01,402.73 1696.01,441.32 v1(1696.26,441.57) ; 1696.01,795.73 1696.01,756.78 v1(1696.26,756.53) ; 1720.01,660.73 1727.76,652.98 v1(1727.76,630.54) ; v1(1727.76,441.57) 1728.01,441.82 1728.01,471.73 ; v1(1727.76,504.57) 1755.01,531.82 1755.01,549 1755.01,561.73 ; v1(1727.76,693.54) 1755.86,693.54 1756.01,693.4 ; v1(1727.76,725.03) 1728.45,725.73 1756.01,725.73 ; v1(1735,1074.01) 1735,1099 1745,1109 ; 1756.01,660.73 1759.26,657.48 v1(1759.26,630.54) ; v1(1771.01,386.73) 1771.01,409.73 ; 1778.59,1265.46 1778.59,1298.59 v1(1779,1299) ; v1(1790.74,756.53) 1790.01,757.27 1790.01,795.73 1790.74,795 ; 1794.01,628.73 1820.43,628.73 v1(1853.74,662.04) ; 1794.01,693.4 1822.1,693.4 v1(1822.24,693.54) ; 1794.99,662.04 1794.01,661.06 1821.26,661.06 v1(1822.24,662.04) ; 1796.57,725.73 1794.01,725.73 1810.06,709.68 1828.6,709.68 1828.92,710 1837.29,710 v1(1853.74,693.54) ; 1799,908 1808,917 ; v1(1822.24,441.57) 1822.24,412.5 1829.01,405.73 ; v1(1822.24,473.07) 1838,457.31 1838,432 1851,419 1851,389.72 1830.01,368.73 ; v1(1822.24,725.03) 1837.59,740.38 1837.59,762.89 1830.01,770.47 1830.01,795.73 ; v1(1853.74,441.57) 1878.01,417.3 1878.01,404.73 ; v1(1853.74,473.07) 1901,425.81 1901,391.72 1878.01,368.73 1879.01,368.73 ; v1(1853.74,504.57) 1869.49,520.32 1900.98,520.32 1922.39,541.73 1933.01,541.73 ; v1(1853.74,725.03) 1853.74,781.74 1866.01,794.01 1866.01,795.73 ; v1(1885.23,504.57) 1928.35,504.57 1933.01,509.23 ; v1(1885.24,725.04) 1868,742.28 1868,764.72 1899.01,795.73 ; v1(1916.73,473.07) 1918.94,475.28 1952.91,475.28 1950.7,473.07
  BOTTOM w6: 787.72,818.6 771.4,834.92 771.4,877.28 789.72,895.6 ; 1042.58,1076.3 1054,1064.88 1054,1013.74 1062.34,1005.4 1085.4,1005.4 ; 1060.01,1093.73 1085.4,1068.34 1085.4,1005.4 ; v1(1101.1,989.7) 1085.4,1005.4
  BOTTOM w8: v1(1006.9,644.3) 1036.88,614.32
  BOTTOM w10: 203.73,457.86 203.73,426.41 v1(204,426.14) ; v1(285,524.14) 302.16,506.98 302.16,490.14 ; v1@302,1180 302.16,1180.16 302.16,1211.66 ; 302.16,457.86 302.16,426.41 v1(302.43,426.14) ; 302.16,1243.94 302.16,1284.16 v1(303,1285) ; v1(380.01,675.73) 381.01,675.73 400.28,695 500.72,695 500.72,649 500.72,603 500.72,557 ; v1@385,426.41 v1(385.27,426.14) 385.27,441.99 403.01,459.73 438.08,459.73 439.95,457.86 ; v1(515,364) 550.03,364 ; v1(515.28,318) 550.31,318 ; 551.03,409 v1(551.03,438.97) ; 583.31,409 619,409 v1(626,402) ; 771.01,723.31 787.72,706.6 ; 771.01,754.2 772.32,754.2 787.72,769.6 787.72,818.6 787.72,826.44 807.01,845.73 831.53,845.73 v1(849.9,864.1) v1@849.9,859.62 ; 820,706.6 849.4,706.6 v1(849.9,707.1) ; 820,818.6 820,769.6 849.6,769.6 v1(849.9,769.9) 895.6,815.6 903.72,815.6 ; 829,1211.28 v1(829,1241) ; 936.97,859 936.97,816.57 936,815.6 961.2,815.6 v1(975.5,801.3) ; v1(944.1,644.3) 944.1,620.7 941,617.6 981,617.6 ; 971.5,1211.28 1019,1211.28 v1(1019,1241) ; 976,694.6 988.5,707.1 v1(1006.9,707.1) 1006.9,731.7 1000,738.6 ; 1029,862.88 1029,886.2 v1(1038.3,895.5) ; 1044,739.6 1044,732.8 v1(1069.7,707.1) ; v1(1069.7,738.5) 1096.9,738.5 1101,742.6 1101.1,742.7 v1(1101.1,769.9) 1101,770 1101,805.6 1101,832.6 v1(1101.1,832.7) ; 1092.29,1093.73 1095.02,1091 v1(1117,1091) ; v1(1163.9,1021.1) 1163.9,998.69 1171.86,990.73 ; 1164,1115.74 1164,1130 v1(1174,1140) ; 1262.28,1044.6 1262,1044.88 1262,1090.6 1324.02,1090.6 v1(1339,1075.62) ; v1(1297.01,560.79) 1297.07,560.73 1365.17,560.73 1365.56,560.34 ; 1400.78,938.45 1400.78,892.72 1400.78,847 v1(1430,847) ; 1400.78,984.17 1400.78,1029.9 v1(1422.89,1052) v1@1423,1052 ; v1@1517.82,748.97 v1(1518.01,748.79) ; 1655.01,400.73 1655.01,431.82 v1(1664.76,441.57) ; v1@1695,1233 v1(1695.18,1233.18) 1727.41,1233.18 ; 1727.41,1265.46 v1(1727.41,1298.41) ; 1778.59,1233.18 v1(1811.82,1233.18) v1@1812,1233 ; 1811.9,1041.01 v1(1855.99,1041.01)
  BOTTOM w12: 975.01,971.87 993.33,971.87 v1(1006.9,958.3) ; 975,971.88 975,990.2 975,1043.14 ; 979.86,1048 979.86,1092
  BOTTOM w13.78: v1(787.1,989.7) 787.1,970.64 802.14,955.6 810.72,955.6 ; 822,895.6 822,899 v1(849.9,926.9) 849.9,948.7 843,955.6 ; 848.72,648.6 849.9,649.78 v1(849.9,675.7) ; 881,648.6 885.6,648.6 v1(912.7,675.7) ; v1(881.3,707.1) 912,737.8 912,739.6 ; v1(881.3,832.7) 881.3,835.62 904.68,859 ; 882.73,935.73 882.73,925.47 v1(912.7,895.5) 941.5,895.5 942.73,896.73 ; 912,771.88 958,771.88 ; 915.01,935.73 935.27,935.73 v1(944.1,926.9) ; 941,585.32 981,585.32 1010,585.32 1039,614.32 1036.88,614.32 ; v1(944.1,707.1) 957,720 957,738.6 ; 957,770.88 958,771.88 ; 975.01,896.73 975.5,896.24 v1(975.5,864.1) ; 975.01,939.59 987.7,926.9 v1(1006.9,926.9) ; v1(975.5,801.3) 975.5,771.88 ; 976,662.32 994.02,644.3 v1(1006.9,644.3) ; 1000,770.88 1000,771.88 ; v1(1006.9,801.3) 1000,794.4 1000,771.88 ; 1012.14,1048 1029.94,1065.8 1032.08,1065.8 1060.01,1093.73 ; 1020.01,1099.87 1012.14,1092 1047.87,1127.73 1084,1127.73 v1(1100,1143.73) ; 1029,830.6 1029,824.74 1052.44,801.3 v1(1069.7,801.3) ; 1038,957.46 1038,927.2 v1(1038.3,926.9) ; 1038,989.74 1038,1020.8 v1(1038.3,1021.1) ; v1(1038.3,675.7) 1039,675 1039,646.6 ; v1(1069.7,644.3) 1098.16,644.3 1099.01,643.45 ; v1(1069.7,675.7) 1098.98,675.7 ; v1(1069.7,769.9) 1067.72,771.88 1044,771.88 1000,771.88 ; v1(1069.7,832.7) 1069.7,860.44 1072.86,863.6 ; v1(1069.7,926.9) 1100.7,926.9 1101,926.6 ; 1105.14,863.6 1132,863.6 ; 1129,1048.14 1133.36,1052.5 v1(1163.9,1052.5) ; v1(1132.5,769.9) 1133.28,769.12 1133.28,742.6 ; v1(1132.5,958.3) 1133.28,957.52 1133.28,926.6 ; v1@1133.28,831.92 v1(1132.5,832.7) 1132.5,863.1 1132,863.6 ; 1164,1083.46 1164.44,1083.9 v1(1195.3,1083.9) 1223.02,1083.9 1229.72,1090.6 1229.72,1044.88 1230,1044.6 ; v1(1195.3,1021.1) 1204.14,1012.26 1204.14,990.73 ; 1252,841.14 1252,853.74 1228.37,877.37 1196,877.37 1182.73,864.1 1132.5,864.1 1132,863.6 ; 1481.84,795.23 1481.84,784.95 v1@1517.82,748.97 ; v1(1512,892) 1557.27,846.73 1615.01,846.73 ; v1@1517.82,748.79 v1(1518.01,748.79) 1536.18,748.79 1585.24,699.73 ; 1617.52,699.73 1639.45,699.73 v1(1664.76,725.03) ; v1(1761,1145) 1794.01,1145 ; 1777.28,1109 1818.01,1109 v1@1834.01,1125 ; v1(1885.23,473.06) 1916.57,441.73 1932.48,441.73 ; v1(1885.23,567.56) 1898.4,580.73 1932.48,580.73 ; v1(1885.23,693.54) 1931.29,693.54 1932.48,694.73 ; v1(1885.23,756.53) 1886.04,755.73 1932.48,755.73 ; v1(1923.01,1156.73) 1956.73,1156.73 1956.73,1198.73 v1(1923.01,1198.73) ; 1925.01,837.73 v1(1964.76,797.98) 1964.76,755.73 1964.76,694.73 1993.01,694.73 1994.01,693.73 ; 1931.01,373.73 1974.01,373.73 1992.01,391.73 v1(1992.01,441.73) 1964.76,441.73 ; 1964.76,580.73 v1(1994.01,580.73) ; 958,771.88 975.5,771.88 ; 975.5,771.88 1000,771.88
  other v1: 104.68,36.73 178.09,36.73 251.51,36.73 324.93,36.73 398.35,36.73 471.76,36.73 545.18,36.73 618.6,36.73 692.01,36.73 765.43,36.73 838.85,36.73 912.27,36.73 985.68,36.73 1059.1,36.73 1132.52,36.73 1205.94,36.73 1279.35,36.73 1352.77,36.73 1426.19,36.73 1499.61,36.73 1573.02,36.73 1646.44,36.73 1719.86,36.73 1793.28,36.73 1866.69,36.73 1940.11,36.73 2013.53,36.73 2086.95,36.73 40.01,63.73 2125.34,63.73 40.01,136.73 2125.34,136.73 40.01,209.73 2125.34,209.73 294.01,269.73 40.01,282.73 2125.34,282.73 1349.01,288.73 1458.84,288.73 1568.68,288.73 1678.51,288.73 1788.34,288.73 1898.18,288.73 2008.01,288.73 839.01,353.73 40.01,355.73 2125.34,355.73 2032.01,360.73 2032.01,423.73 40.01,428.73 2125.34,428.73 921.01,445 2032.01,486.73 40.01,501.73 2125.34,501.73 100.01,534.73 2032.01,549.73 40.01,574.73 2125.34,574.73 2032.01,612.73 286.01,620.73 1999.01,639.73 1951.01,640.73 40.01,647.73 2125.34,647.73 98.01,658.73 286.01,677.73 40.01,720.73 2125.34,720.73 40.01,793.73 2125.34,793.73 1790.01,836.73 1841.51,836.73 1893.01,836.73 1740.01,837.73 40.01,866.73 2125.34,866.73 1772,871.73 1553.01,891.73 1856,939 40.01,939.73 2129.34,939.73 1623,954 1857,965 818.5,989.7 1856,991 1623,1011 1651.5,1011.73 40.01,1012.73 2129.34,1012.73 40.01,1085.73 2125.34,1085.73 1620,1094.73 1648,1094.73 1684,1095.73 1833.01,1125 1461,1128 1648,1129.73 1684,1129.73 1620,1130.73 2034.01,1145 40.01,1158.73 2125.34,1158.73 2033.01,1169 1956.73,1178.73 307.01,1180.73 789.01,1182.73 2032,1195.73 1137.01,1213 2032,1220.73 40.01,1231.73 2128.34,1231.73 2053.01,1269 222.01,1287.73 1224.01,1298.73 1055.01,1302.73 40.01,1304.73 2128.34,1304.73 1973.01,1323.73 2035.01,1324.73 1541.01,1357.2 40.01,1377.73 2125.34,1377.73 40.01,1450.73 2125.34,1450.73 40.01,1523.73 2125.34,1523.73 104.01,1536.73 177.43,1536.73 250.84,1536.73 324.26,1536.73 397.68,1536.73 471.1,1536.73 544.51,1536.73 617.93,1536.73 691.35,1536.73 764.77,1536.73 838.18,1536.73 911.6,1536.73 985.02,1536.73 1058.44,1536.73 1131.85,1536.73 1205.27,1536.73 1278.69,1536.73 1352.11,1536.73 1425.52,1536.73 1498.94,1536.73 1572.36,1536.73 1645.78,1536.73 1719.19,1536.73 1792.61,1536.73 1866.03,1536.73 1939.44,1536.73 2012.86,1536.73 2086.28,1536.73

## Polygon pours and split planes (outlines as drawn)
no net on TOP "TOP-No Net" (hatched 90Degree grid 4 track 5, remove dead copper, pour order 1004): 1741,977 1741,1020 1634,1020 1614,1020 1614,936 1614,932 1734,932 1741,932 1741,977
no net on TOP "TOP-No Net" (hatched 90Degree grid 4 track 5, remove dead copper, pour order 1003): 1792,939 1792,1006 1855,1006 1876,1006 1876,951 1876,929 1811,929 1792,929 1792,939
no net on TOP "TOP-No Net" (hatched 90Degree grid 4 track 5, remove dead copper, pour order 1000): 1623.01,1204.73 1700.01,1204.73 1700.01,1146.73 1700.01,1086.73 1628.01,1086.73 1609.01,1086.73 1609.01,1134.73 1609.01,1204.73 1623.01,1204.73
no net on TOP "TOP-No Net" (hatched 90Degree grid 4 track 5, remove dead copper, pour order 1000): 0,1574.8 2165.35,1574.8 2165.35,1204.73 2165.35,0 1443.01,0 0,0 0,1574.8
no net on BOTTOM "TOP-No Net" (hatched 90Degree grid 4 track 5, remove dead copper, pour order 1004): 1093.01,837.73 1213.01,837.73 1213.01,818 1265.01,818 1265.01,746.73 1093.01,746.73
no net on BOTTOM "TOP-No Net" (hatched 90Degree grid 4 track 5, remove dead copper, pour order 1009): 1800,1000 1874,1000 1874,957 1800,957
no net on BOTTOM "TOP-No Net" (hatched 90Degree grid 4 track 5, remove dead copper, pour order 1008): 1668,984 1668,1062 1745,1062 1765,1062 1765,969 1765,935 1745,935 1730,935 1730,971 1730,984 1668,984
no net on BOTTOM "TOP-No Net" (hatched 90Degree grid 4 track 5, remove dead copper, pour order 1007): 1668,926 1668,866 1700,866 1827,866 1827,882 1827,923 1807,923 1807,926 1668,926
no net on BOTTOM "TOP-No Net" (hatched 90Degree grid 4 track 5, remove dead copper, pour order 1001): 2063.01,1298.17 2063.01,1137.73 1982.01,1137.73 1982.01,1298.17
no net on BOTTOM "TOP-No Net" (hatched 90Degree grid 4 track 5, remove dead copper, pour order 1002): 1964.01,1287.73 1964.01,1150.73 1844.01,1150.73 1844.01,1287.73
no net on BOTTOM "TOP-No Net" (hatched 90Degree grid 4 track 5, remove dead copper, pour order 1003): 1656.01,873.73 1591.01,873.73 1591.01,885.73 1591.01,1029.43 1685,1029.43 1754.01,1029.43 1754.01,973 1754.01,966.73 1677.01,966.73 1656.01,966.73 1656.01,873.73
no net on BOTTOM "TOP-No Net" (hatched 90Degree grid 4 track 5, remove dead copper, pour order 1001): 0,1574.8 2165.35,1574.8 2165.35,1204.73 2165.35,0 1443.01,0 0,0 0,1574.8
no net on ART04 "TOP-No Net" (hatched 90Degree grid 4 track 5, remove dead copper, pour order 1006): 1700.01,1087.73 1700.01,1348.73 1654.01,1348.73 1654.01,1433.73 1585.01,1433.73 1563.01,1433.73 1563.01,1390.73 1563.01,1071.73 1636.01,1071.73 1700.01,1071.73 1700.01,1087.73
no net on ART04 "TOP-No Net" (hatched 90Degree grid 4 track 5, remove dead copper, pour order 1007): 1029.01,899.73 1029.01,938.4 1142.34,1051.73 1744.01,1051.73 1744.01,1308.73 1797.01,1308.73 1797.01,1431.73 1850.01,1431.73 1850.01,1081.73 1817.01,1081.73 1817.01,899.73
no net on ART04 "TOP-No Net" (hatched 90Degree grid 4 track 5, remove dead copper, pour order 1005): 1932.01,924.73 1932.01,1443.73 1869.01,1443.73 1869.01,1059.73 1835.01,1059.73 1835.01,924.73
no net on ART04 "TOP-No Net" (hatched 90Degree grid 4 track 5, remove dead copper, pour order 1002): 0,1574.8 2165.35,1574.8 2165.35,1204.73 2165.35,0 1443.01,0 0,0 0,1574.8
no net on ART03 "TOP-No Net" (hatched 90Degree grid 4 track 5, remove dead copper, pour order 1008): 1006.9,889.23 1169.62,889.23 1256.01,975.62 1256.01,1168.73 1815.01,1168.73 1815.01,1445 1670.01,1445 1670.01,1328.73 1006.9,1328.73
no net on ART03 "TOP-No Net" (hatched 90Degree grid 4 track 5, remove dead copper, pour order 1009): 1186.01,872.73 1278.01,964.73 1278.01,1152.73 1701.01,1152.73 1701.01,1053.73 1424,1053.73 1424,883.72 1318.01,777.73 1142.01,777.73 1142.01,695.73 840.01,695.73 840.01,872.73
no net on ART03 "TOP-No Net" (hatched 90Degree grid 4 track 5, remove dead copper, pour order 1003): 0,1574.8 2165.35,1574.8 2165.35,1204.73 2165.35,0 1443.01,0 0,0 0,1574.8
no net on GND02 (split plane): 2145.26,20.1 20.1,20.1 20.1,1554.71 2145.26,1554.71
no net on PWR05 (split plane): 2105.26,1462.83 1949.01,1462.83 1947.06,1462.44 1945.41,1461.33 1944.3,1459.68 1943.91,1457.73 1943.91,1305.73 1943.91,930.84 1867.9,854.83 1024.01,854.83 1022.06,854.44 1020.41,853.33 977.41,810.33 976.3,808.68 975.91,806.73 975.91,412.73 976.3,410.78 977.41,409.13 1091.41,295.13 1093.06,294.02 1095.01,293.63 2105.26,293.63 2105.26,60.09 60.09,60.09 60.09,1514.71 2105.26,1514.71
no net on PWR05 (split plane): 2105.26,303.83 1097.12,303.83 986.11,414.84 986.11,804.62 1026.12,844.63 1870.01,844.63 1871.96,845.02 1873.61,846.13 1952.61,925.13 1953.72,926.78 1954.11,928.73 1954.11,1305.73 1954.11,1452.63 2105.26,1452.63

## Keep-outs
Keep-Out Layer:
  the board outline again, w5

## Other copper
TOP:
  rectangle: 1664,945 1734,998
  pour cut-out: 1543.01,1253.73 1543.01,1212.73 1442.01,1212.73 1442.01,1253.73
  pour cut-out: 1496.01,1045.73 1560.01,1045.73 1560.01,1016.73 1496.01,1016.73
  pour cut-out: 1400.78,1066.73 1437.01,1066.73 1437.01,1030.73 1400.78,1030.73
  pour cut-out: 1737.01,1090.73 1808.96,1090.73 1808.96,1024.73 1783.01,1024.73 1783.01,884.73 1737.01,884.73
  pour cut-out: 1273.01,583.73 1322.26,583.73 1322.26,541.01 1273.01,541.01
  text "高端、高速PCB设计文件与你共分享 PCB联盟网 www.pcbbar.com  QQ群:374116257" at -1505,2048 h196.85
  text "TOP" at 28,1718 h60
ART03:
  rectangle: 1710.01,1369 1788.01,1445
  pour cut-out: 1414.01,773.73 1774.86,773.73 1774.86,619.73 1414.01,619.73
  pour cut-out: 1053.01,665.73 1123.01,665.73 1123.01,581.5 1053.01,581.5
  pour cut-out: 1594.01,515.73 1686.01,515.73 1686.01,390.73 1594.01,390.73
  pour cut-out: 613.01,705.73 613.01,440.73 899.01,440.73 899.01,203.73 168.98,203.73 168.98,705.73
  pour cut-out: 149.01,180.73 1632,180.73 1632,78.73 149.01,78.73
  text "ART03" at 587,1718 h60
ART04:
  rectangle: 1869.01,1368.73 1948,1433
  rectangle: 1810.01,1366.73 1850.01,1430.73
  rectangle: 1569.01,1357.73 1632,1422.73
  pour cut-out: 404.01,485.73 585.01,485.73 585.01,418.73 416.01,418.73 416.01,486.73
  pour cut-out: 217.01,693 470.01,693 470.01,582.73 217.01,582.73
  pour cut-out: 184.01,1399.73 452.01,1399.73 452.01,953.1 184.01,953.1
  pour cut-out: 101.01,1513.73 1458.41,1513.73 1458.41,1416.73 1343.01,1416.73 1343.01,1138.73 1280.01,1075.73 1093.01,1075.73 1093.01,1173.73 1267.01,1173.73 1267.01,1390.73 97.01,1390.73 97.01,1517.73
  pour cut-out: 1059.01,896.73 1087.01,896.73 1087.01,877 1059.01,877
  text "ART04" at 937,1719 h60
BOTTOM:
  rectangle: 1196,784.32 1255,816
  rectangle: 1842.5,932 1875,976
  rectangle: 1745,873 1814,908
  rectangle: 1811,965 1858,991
  rectangle: 1646.68,964.82 1739.01,997
  rectangle: 1161.81,758.73 1204,827.73
  pour cut-out: 1766.01,1091.73 1799.01,1091.73 1799.01,1043.73 1766.01,1043.73
  pour cut-out: 1292.01,1041.73 1356.01,1041.73 1356.01,1004 1292.01,1004
  text "BOTTOM" at 2056,1718 h60
GND02 (plane layer: these items are gaps in the copper):
  text "GND02" at 242,1719 h60
PWR05 (plane layer: these items are gaps in the copper):
  lines w10: 2165.35,1457.73 1949.01,1457.73 1949.01,1305.73 1949.01,928.73 1870.01,849.73 1055.01,849.73 1024.01,849.73 981.01,806.73 981.01,412.73 1095.01,298.73 2176.01,298.73
  text "PWR05" at 1311,1716 h60

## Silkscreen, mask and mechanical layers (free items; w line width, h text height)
Top Overlay:
  lines w5: 569.01,1157.73 790.01,1157.73 790.01,1323.73 597.01,1323.73 569.01,1323.73 569.01,1157.73 ; 1050.01,1128.73 1388.01,1128.73 1388.01,1361.73 1066.01,1361.73 1050.01,1361.73 1050.01,1128.73
  text "A" at 1078.01,1329.73 h25
  text "A" at 734.01,1287.73 h25
Bottom Overlay:
  lines w5: 868.01,859.73 879.01,859.73 ; 893.01,795.91 1166.01,795.91 1166.01,295.73 900.69,295.73 900.69,695.73 875.01,695.73 875.01,795.91 963.01,795.91 ; 942.01,1011.73 975.01,1011.73 975.01,999.73 ; 955.69,817.73 968.01,817.73 ; 1024.01,888.73 1024.01,898.73 ; 1127.01,1078.73 1127.01,1099.73
Drill Drawing:
  text ".Legend" at 2356,-6 h30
